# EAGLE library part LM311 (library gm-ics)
COMPARATOR
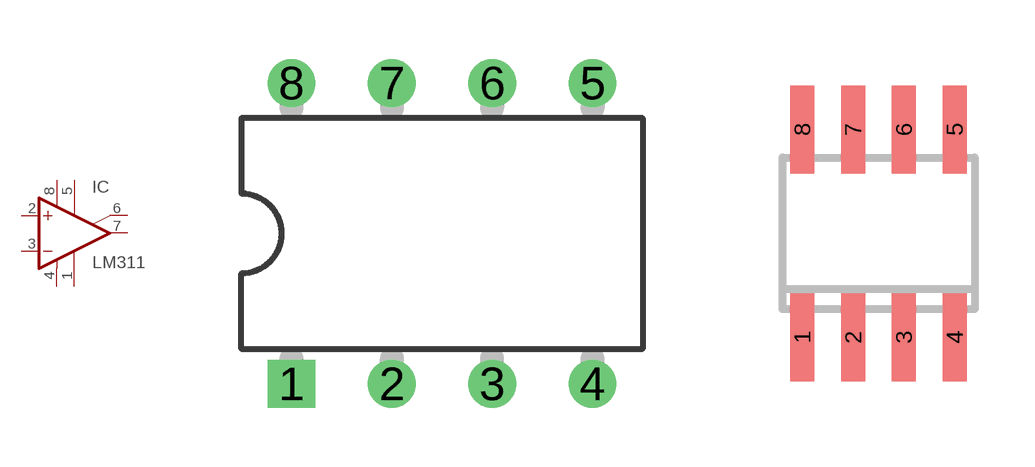
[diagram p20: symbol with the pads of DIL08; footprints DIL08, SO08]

Designator prefix IC

## LM311N  [DIL08]
1  GND  pas
2  +IN  in
3  -IN  in
4  V-  pwr
5  ON  pas
6  ON/STR  pas
7  OUT  out
8  V+  pwr

## LM311D  [SO08]
Pads as for DIL08

## Footprint DIL08 (pad centres in mm)
Dual In Line Package
drill 0.7 square: 1 -3.81,-3.81
drill 0.7 round: 2 -1.27,-3.81; 3 1.27,-3.81; 4 3.81,-3.81; 5 3.81,3.81; 6 1.27,3.81; 7 -1.27,3.81; 8 -3.81,3.81

## Footprint SO08 (pad centres in mm)
Small Outline Package 8 NS Package M08A
smd 0.6 x 2.2: 1 -1.905,-2.6; 2 -0.635,-2.6; 3 0.635,-2.6; 4 1.905,-2.6; 5 1.905,2.6; 6 0.635,2.6; 7 -0.635,2.6; 8 -1.905,2.6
